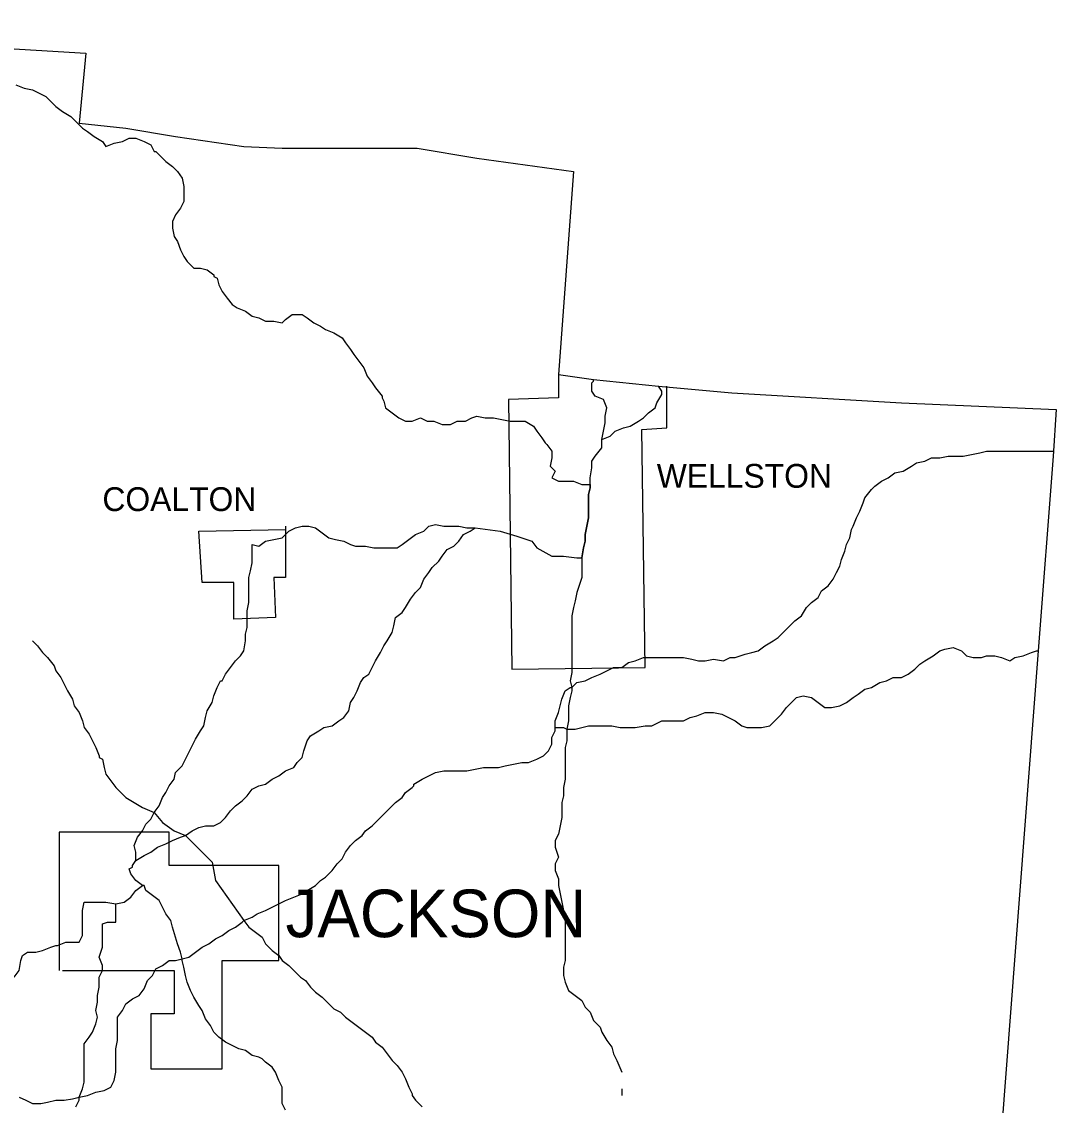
# Model space of a CAD drawing. Extents: x 0 to 40.2, y 0 to 22.
# Drawn here: x 7.207 to 8.054, y 17.657 to 18.545 of the extents above; entities that cross this region are included whole.
import ezdxf

# ---------------------------------------------------------------- set-up
doc = ezdxf.new("R2010")
doc.units = 0
doc.layers.add('Default', color=7, linetype='Continuous')

msp = doc.modelspace()

# ---------------------------------------------------------------- linework, layer by layer
at = {"layer": 'Default'}
for points in [[(6.86238, 18.54502), (7.0369, 18.53275), (7.11189, 18.52866), (7.14597, 18.52593), (7.25914, 18.51912), (7.25368, 18.46185), (7.29186, 18.45776), (7.33276, 18.45095), (7.38866, 18.44277), (7.42002, 18.4414), (7.47729, 18.4414), (7.53046, 18.4414), (7.57954, 18.43322), (7.65862, 18.42231), (7.64635, 18.25598)], [(7.20187, 18.49321), (7.20869, 18.49049), (7.21551, 18.48912), (7.22096, 18.4864), (7.22642, 18.48367), (7.23051, 18.47958), (7.2346, 18.47549), (7.24005, 18.4714), (7.24687, 18.46731), (7.25096, 18.46322), (7.25641, 18.45776), (7.2605, 18.45504), (7.26596, 18.45095), (7.27277, 18.44686), (7.2755, 18.44277), (7.28232, 18.44549), (7.28913, 18.44686), (7.29459, 18.44958), (7.30004, 18.44958), (7.30686, 18.44686), (7.31231, 18.44413), (7.31504, 18.43868)], [(7.31504, 18.43868), (7.3164, 18.43868), (7.3164, 18.43868), (7.32049, 18.43459), (7.32458, 18.43049), (7.33004, 18.4264), (7.33413, 18.42231), (7.33822, 18.41686), (7.33958, 18.41004), (7.33958, 18.40459), (7.33958, 18.39777), (7.33685, 18.39232), (7.33276, 18.38687), (7.33004, 18.38141), (7.33004, 18.37596), (7.3314, 18.36914), (7.33413, 18.36505), (7.33685, 18.35823), (7.33958, 18.35278), (7.34231, 18.34869), (7.34776, 18.34324), (7.35321, 18.34324), (7.35867, 18.34187), (7.36412, 18.33778)], [(7.36412, 18.33778), (7.36412, 18.33642), (7.36412, 18.33642), (7.36685, 18.33506), (7.36821, 18.3296), (7.37094, 18.32415), (7.37503, 18.31869), (7.37912, 18.31324), (7.38321, 18.31051), (7.39003, 18.30779), (7.39548, 18.3037), (7.40093, 18.30233), (7.40639, 18.29961), (7.4132, 18.29961), (7.42002, 18.29824), (7.42275, 18.30097), (7.4282, 18.30506), (7.43638, 18.30506), (7.44047, 18.30233), (7.44593, 18.29824), (7.45138, 18.29552), (7.45547, 18.29279), (7.46229, 18.29006), (7.4691, 18.28597), (7.47183, 18.28188), (7.47592, 18.27643), (7.47865, 18.27234), (7.48274, 18.26688), (7.48683, 18.26143), (7.48956, 18.25461), (7.49365, 18.24916), (7.49637, 18.24507), (7.50183, 18.23825)], [(7.64635, 18.25598), (7.64635, 18.23689), (7.60545, 18.23553), (7.60817, 18.01465), (7.71725, 18.01601), (7.71452, 18.21098), (7.73497, 18.21235), (7.73497, 18.24643)], [(7.64635, 18.25598), (7.67498, 18.25189), (7.72815, 18.24643), (7.78815, 18.24098), (7.92721, 18.2328), (8.05401, 18.22735)], [(7.6818, 18.2028), (7.68316, 18.20962), (7.68453, 18.21644), (7.68453, 18.22189), (7.68589, 18.22871), (7.68316, 18.23553), (7.67634, 18.23825), (7.67362, 18.24234), (7.67362, 18.24916), (7.67498, 18.25052), (7.67498, 18.25189)], [(7.6818, 18.2028), (7.68862, 18.20553), (7.69271, 18.20962), (7.69952, 18.21235), (7.70498, 18.21371), (7.71179, 18.2178), (7.71588, 18.22053), (7.71997, 18.22462), (7.72543, 18.22871), (7.72679, 18.2328), (7.73088, 18.23962), (7.73088, 18.24234), (7.72815, 18.24643)], [(7.50183, 18.23825), (7.50183, 18.23689), (7.50319, 18.23416), (7.50455, 18.22871), (7.51001, 18.22462), (7.51546, 18.22053), (7.52091, 18.2178), (7.52637, 18.2178), (7.53319, 18.22053), (7.53864, 18.2178), (7.54409, 18.2178), (7.55091, 18.21507), (7.55773, 18.21507), (7.56318, 18.2178), (7.57, 18.2178), (7.57545, 18.22053), (7.57954, 18.22189), (7.58636, 18.22053), (7.59318, 18.22053), (7.59999, 18.21916), (7.60681, 18.2178), (7.61363, 18.2178), (7.61908, 18.2178), (7.6259, 18.21371), (7.62863, 18.20962), (7.63272, 18.20417), (7.63544, 18.20008)], [(8.05401, 18.22735), (8.05129, 18.18917), (8.03901, 18.02965), (8.00902, 17.63698), (7.9872, 17.36294), (7.96948, 17.16524), (7.96812, 17.14206), (7.9463, 16.89937), (7.68044, 16.92528), (7.52501, 16.93891)], [(7.63544, 18.20008), (7.63681, 18.19871), (7.6409, 18.19326), (7.6409, 18.18781), (7.63953, 18.18099), (7.64362, 18.1769), (7.6409, 18.17144), (7.64635, 18.16872), (7.6518, 18.16872), (7.65862, 18.16872), (7.66544, 18.16599), (7.67225, 18.16599)], [(7.67225, 18.16599), (7.67225, 18.17144), (7.67362, 18.17963), (7.67362, 18.18508), (7.67634, 18.18917), (7.6818, 18.19599), (7.6818, 18.20144), (7.6818, 18.2028), (7.6818, 18.2028)], [(7.88768, 18.13191), (7.8904, 18.13872), (7.89313, 18.14418), (7.89586, 18.15099), (7.89722, 18.15508), (7.90267, 18.1619), (7.9054, 18.16463), (7.91085, 18.16872), (7.91631, 18.17144), (7.92176, 18.17554), (7.92858, 18.1769), (7.93539, 18.18099), (7.93949, 18.18372), (7.9463, 18.18508), (7.95176, 18.18781), (7.95857, 18.18781), (7.96539, 18.18917), (7.97084, 18.18917), (7.97766, 18.18917), (7.98448, 18.19053), (7.9913, 18.1919), (7.99675, 18.19326), (8.00357, 18.19326), (8.01038, 18.19326), (8.01584, 18.19326), (8.02265, 18.19326), (8.02947, 18.19326), (8.03629, 18.19326), (8.04311, 18.19326), (8.04992, 18.19326), (8.05129, 18.19326)], [(7.66544, 18.106), (7.6668, 18.11418), (7.66816, 18.11963), (7.66816, 18.12509), (7.66953, 18.13191), (7.67089, 18.13872), (7.67089, 18.14418), (7.67089, 18.15099), (7.67089, 18.15781), (7.67225, 18.16326), (7.67225, 18.16599)], [(7.67225, 18.16599), (7.67225, 18.16326), (7.67089, 18.15781), (7.67089, 18.15099), (7.67089, 18.14418), (7.67089, 18.13872), (7.66953, 18.13191), (7.66816, 18.12509), (7.66816, 18.11963), (7.6668, 18.11418), (7.66544, 18.106)], [(7.42275, 18.13191), (7.42275, 18.08964), (7.4132, 18.08964), (7.41457, 18.05692), (7.38048, 18.05555), (7.38048, 18.08555), (7.35458, 18.08555), (7.35185, 18.12782), (7.42275, 18.12918)], [(7.39548, 18.11691), (7.40093, 18.11554), (7.40639, 18.11963), (7.4132, 18.121), (7.42002, 18.12236), (7.42548, 18.12782), (7.43093, 18.13054), (7.43638, 18.13191), (7.44184, 18.13191), (7.44729, 18.13054), (7.45274, 18.12645), (7.4582, 18.12236), (7.46365, 18.121), (7.47047, 18.11963), (7.47592, 18.11691), (7.48001, 18.11554), (7.48138, 18.11554)], [(7.48138, 18.11554), (7.48819, 18.11554), (7.49501, 18.11418), (7.50183, 18.11418), (7.50864, 18.11418), (7.5141, 18.11418), (7.51819, 18.11691), (7.52364, 18.121), (7.5291, 18.12509), (7.53591, 18.12782), (7.54, 18.13191), (7.54546, 18.13327), (7.55227, 18.13191), (7.55909, 18.13191), (7.56454, 18.13191), (7.57136, 18.13054), (7.57818, 18.13054), (7.57818, 18.13054)], [(7.4841, 18.00374), (7.48683, 18.00783), (7.49092, 18.01056), (7.49365, 18.01601), (7.49637, 18.02147), (7.50046, 18.02829), (7.50319, 18.03374), (7.50592, 18.03783), (7.51001, 18.04465), (7.51137, 18.0501), (7.51273, 18.05692), (7.51819, 18.06101), (7.52091, 18.0651), (7.52501, 18.07192), (7.5291, 18.07737), (7.53319, 18.08146), (7.53591, 18.08828), (7.54, 18.09373), (7.54273, 18.09782), (7.54818, 18.10327), (7.55091, 18.10736), (7.555, 18.11282), (7.56045, 18.11554), (7.56454, 18.11963), (7.56863, 18.12509), (7.57409, 18.12782), (7.57818, 18.13054), (7.57818, 18.13054)], [(7.57818, 18.13054), (7.59863, 18.12782), (7.61226, 18.12373), (7.62453, 18.11963), (7.62863, 18.11418), (7.6409, 18.10736), (7.65044, 18.10736), (7.66135, 18.106), (7.66544, 18.106)], [(7.77315, 18.02283), (7.78133, 18.02147), (7.78678, 18.0242), (7.79087, 18.0242), (7.79905, 18.02692), (7.80451, 18.02829), (7.80996, 18.02965), (7.81541, 18.03374), (7.82223, 18.03783), (7.82632, 18.04056), (7.83177, 18.04601), (7.83723, 18.05146), (7.83996, 18.05419), (7.84541, 18.05828), (7.8495, 18.0651), (7.85359, 18.06919), (7.85904, 18.07328), (7.86177, 18.07873), (7.86722, 18.08282), (7.87131, 18.08828), (7.87404, 18.09373), (7.87677, 18.09918), (7.87813, 18.10464), (7.88086, 18.11145), (7.88222, 18.11691), (7.88495, 18.12236), (7.88631, 18.12918), (7.88768, 18.13191)], [(7.37094, 18.00511), (7.37367, 18.01056), (7.37776, 18.01601), (7.38185, 18.02147), (7.38594, 18.02556), (7.38866, 18.02965), (7.39003, 18.03783), (7.39003, 18.04328), (7.39139, 18.04874), (7.39139, 18.05555), (7.39139, 18.06237), (7.39275, 18.06919), (7.39275, 18.07601), (7.39275, 18.08146), (7.39275, 18.08964), (7.39412, 18.09509), (7.39548, 18.10191), (7.39548, 18.10736), (7.39548, 18.11418), (7.39548, 18.11554), (7.39548, 18.11691)], [(7.66544, 18.106), (7.66544, 18.10191), (7.66544, 18.09509), (7.66544, 18.08964), (7.66271, 18.08146), (7.66135, 18.07737), (7.65998, 18.07055), (7.65862, 18.0651), (7.65726, 18.05828), (7.65726, 18.05283), (7.65726, 18.04465), (7.65726, 18.03783), (7.65726, 18.03101), (7.65726, 18.02556), (7.65726, 18.01874), (7.65726, 18.01192), (7.65589, 18.00511), (7.65726, 17.99965)], [(7.21551, 18.03783), (7.2196, 18.03374), (7.22369, 18.02829), (7.22778, 18.0242), (7.23323, 18.01738), (7.2346, 18.01329), (7.23869, 18.00783), (7.24141, 18.00238), (7.24414, 17.99693), (7.24823, 17.99011), (7.24959, 17.98466), (7.25368, 17.9792), (7.25641, 17.97239), (7.25777, 17.96693), (7.26186, 17.96148), (7.26459, 17.95602), (7.26732, 17.95057), (7.27005, 17.94375), (7.27005, 17.94239), (7.27277, 17.94103), (7.27277, 17.94103)], [(7.89177, 17.9942), (7.89722, 17.99829), (7.90267, 17.99965), (7.90949, 18.00374), (7.91494, 18.00511), (7.9204, 18.00783), (7.92721, 18.00783), (7.93267, 18.01056), (7.93812, 18.01465), (7.94221, 18.01874), (7.9463, 18.02147), (7.95312, 18.02556), (7.95857, 18.02965), (7.96266, 18.03101), (7.96948, 18.03238), (7.9763, 18.02965), (7.98039, 18.02556), (7.98584, 18.0242), (7.99266, 18.0242), (7.99675, 18.02556), (8.00357, 18.02556), (8.00902, 18.0242), (8.01584, 18.02147), (8.01993, 18.0242), (8.02674, 18.02556), (8.03356, 18.02829), (8.03765, 18.02965), (8.03765, 18.02965), (8.03901, 18.02965)], [(7.65726, 17.99965), (7.66135, 18.00374), (7.66816, 18.00511), (7.67362, 18.00783), (7.68044, 18.01056), (7.68589, 18.01329), (7.69134, 18.01601), (7.69816, 18.01601), (7.70361, 18.02011), (7.70907, 18.02147), (7.71588, 18.0242), (7.72134, 18.0242), (7.72679, 18.0242), (7.73497, 18.0242), (7.74179, 18.0242), (7.74861, 18.0242), (7.75542, 18.02283), (7.76088, 18.02147), (7.76633, 18.02147), (7.77315, 18.02283), (7.77315, 18.02283)], [(7.29868, 17.87013), (7.3014, 17.87695), (7.30549, 17.8824), (7.30822, 17.88785), (7.31231, 17.89194), (7.31504, 17.8974), (7.31913, 17.90285), (7.32186, 17.90967), (7.32458, 17.91376), (7.32731, 17.91921), (7.3314, 17.92467), (7.33276, 17.93012), (7.33822, 17.93557), (7.34094, 17.94103), (7.34367, 17.94648), (7.3464, 17.95193), (7.34912, 17.95739), (7.35321, 17.9642), (7.35594, 17.9683), (7.3573, 17.97511), (7.35867, 17.98057), (7.36276, 17.98738), (7.36412, 17.99284), (7.36685, 17.99965), (7.36958, 18.00511), (7.37094, 18.00511), (7.37094, 18.00511)], [(7.30004, 17.85786), (7.30686, 17.86195), (7.31231, 17.86468), (7.31777, 17.86877), (7.32458, 17.87149), (7.33004, 17.87422), (7.33685, 17.87695), (7.34094, 17.87831), (7.3464, 17.8824), (7.35185, 17.88513), (7.3573, 17.88649), (7.36412, 17.88649), (7.36958, 17.88922), (7.37367, 17.89331), (7.37776, 17.89876), (7.38185, 17.90285), (7.3873, 17.90694), (7.39139, 17.91103), (7.39548, 17.91649), (7.40093, 17.91921), (7.40639, 17.92058), (7.41184, 17.92467), (7.41729, 17.92739), (7.42275, 17.93148), (7.42957, 17.93421), (7.43229, 17.9383), (7.43638, 17.94239), (7.43775, 17.94784), (7.44047, 17.95602), (7.4432, 17.96011), (7.45002, 17.9642), (7.45411, 17.96693), (7.46092, 17.9683), (7.46638, 17.97239), (7.47047, 17.97511), (7.47456, 17.98057), (7.47592, 17.98738), (7.47865, 17.99147), (7.48138, 17.99693), (7.4841, 18.00374), (7.4841, 18.00374), (7.4841, 18.00374)], [(7.64362, 17.96693), (7.64362, 17.97239), (7.64635, 17.9792), (7.64771, 17.98466), (7.64908, 17.99011), (7.6518, 17.99693), (7.65589, 17.99965), (7.65726, 17.99965)], [(7.65726, 17.99965), (7.65726, 17.99693), (7.65589, 17.99147), (7.65453, 17.98466), (7.65453, 17.9792), (7.65453, 17.97239), (7.65317, 17.96557)], [(7.77315, 17.9792), (7.77996, 17.97784), (7.78542, 17.97511), (7.79087, 17.97239), (7.79633, 17.9683), (7.80042, 17.96693), (7.80723, 17.96693), (7.81269, 17.96693), (7.8195, 17.9683), (7.82359, 17.97239), (7.82905, 17.97784), (7.83314, 17.98329), (7.83723, 17.98738), (7.84132, 17.99147), (7.84677, 17.99284), (7.85359, 17.99147), (7.85904, 17.98738), (7.8645, 17.98329), (7.86995, 17.98329), (7.87677, 17.98466), (7.88222, 17.98738), (7.88768, 17.99147), (7.89177, 17.9942), (7.89177, 17.9942), (7.89177, 17.9942)], [(7.65317, 17.96557), (7.65998, 17.96557), (7.66544, 17.96693), (7.67089, 17.9683), (7.67771, 17.9683), (7.68453, 17.9683), (7.68998, 17.9683), (7.6968, 17.96693), (7.70225, 17.96693), (7.70907, 17.96693), (7.71725, 17.9683), (7.7227, 17.9683), (7.73088, 17.97239), (7.73497, 17.97239), (7.74179, 17.97239), (7.74861, 17.97239), (7.75406, 17.97511), (7.75951, 17.97648), (7.76633, 17.9792), (7.77178, 17.9792), (7.77315, 17.9792), (7.77315, 17.9792)], [(7.52773, 17.92058), (7.53455, 17.92467), (7.54, 17.92739), (7.54546, 17.93012), (7.55227, 17.93148), (7.55909, 17.93148), (7.56454, 17.93148), (7.57136, 17.93148), (7.57818, 17.93285), (7.585, 17.93421), (7.59181, 17.93421), (7.59727, 17.93421), (7.60272, 17.93557), (7.60954, 17.93694), (7.61635, 17.9383), (7.62181, 17.9383), (7.62863, 17.94103), (7.63408, 17.94375), (7.63817, 17.94784), (7.6409, 17.9533), (7.6409, 17.95875), (7.64362, 17.9642), (7.64362, 17.96693)], [(7.52773, 17.92058), (7.53455, 17.92467), (7.54, 17.92739), (7.54546, 17.93012), (7.55227, 17.93148), (7.55909, 17.93148), (7.56454, 17.93148), (7.57136, 17.93148), (7.57818, 17.93285), (7.585, 17.93421), (7.59181, 17.93421), (7.59727, 17.93421), (7.60272, 17.93557), (7.60954, 17.93694), (7.61635, 17.9383), (7.62181, 17.9383), (7.62863, 17.94103), (7.63408, 17.94375), (7.63817, 17.94784), (7.6409, 17.9533), (7.6409, 17.95875), (7.64362, 17.9642), (7.64362, 17.96693)], [(7.64362, 17.96693), (7.65044, 17.96693), (7.65317, 17.96557)], [(7.65317, 17.96557), (7.65317, 17.9642), (7.65317, 17.95602), (7.6518, 17.95057), (7.6518, 17.94375), (7.6518, 17.9383), (7.6518, 17.93148), (7.6518, 17.92467), (7.65044, 17.91785), (7.65044, 17.91103), (7.64908, 17.90558), (7.64908, 17.89876), (7.64908, 17.89331), (7.64771, 17.88649), (7.64635, 17.87967), (7.64362, 17.87422), (7.64362, 17.86877), (7.64635, 17.86058), (7.64362, 17.85513), (7.64362, 17.84968), (7.64635, 17.84286), (7.64635, 17.83741), (7.64771, 17.83059), (7.64908, 17.82377), (7.65044, 17.81696)], [(7.27277, 17.94103), (7.27414, 17.93421), (7.2755, 17.92876), (7.27959, 17.9233), (7.28368, 17.91785), (7.29186, 17.90967), (7.30549, 17.90149), (7.31504, 17.8974), (7.32186, 17.88922), (7.3314, 17.8824), (7.34094, 17.87831), (7.36276, 17.85649), (7.36548, 17.8415), (7.38866, 17.80877)], [(7.38866, 17.80877), (7.39548, 17.8115), (7.39957, 17.81423), (7.40639, 17.81696), (7.41184, 17.81968), (7.41729, 17.82241), (7.42275, 17.82514), (7.42957, 17.82786), (7.43638, 17.83059), (7.44047, 17.83332), (7.44729, 17.83741), (7.45138, 17.8415), (7.45547, 17.84422), (7.46092, 17.84968), (7.46501, 17.85513), (7.4691, 17.85922), (7.47183, 17.86468), (7.47592, 17.87013), (7.48001, 17.87422), (7.48547, 17.87831), (7.48819, 17.8824), (7.49365, 17.88649), (7.4991, 17.89194), (7.50319, 17.89603), (7.50728, 17.90012), (7.51273, 17.90558), (7.51819, 17.90967), (7.52091, 17.91376), (7.52637, 17.91785), (7.52773, 17.91921), (7.52773, 17.92058)], [(7.38866, 17.80877), (7.39548, 17.8115), (7.39957, 17.81423), (7.40639, 17.81696), (7.41184, 17.81968), (7.41729, 17.82241), (7.42275, 17.82514), (7.42957, 17.82786), (7.43638, 17.83059), (7.44047, 17.83332), (7.44729, 17.83741), (7.45138, 17.8415), (7.45547, 17.84422), (7.46092, 17.84968), (7.46501, 17.85513), (7.4691, 17.85922), (7.47183, 17.86468), (7.47592, 17.87013), (7.48001, 17.87422), (7.48547, 17.87831), (7.48819, 17.8824), (7.49365, 17.88649), (7.4991, 17.89194), (7.50319, 17.89603), (7.50728, 17.90012), (7.51273, 17.90558), (7.51819, 17.90967), (7.52091, 17.91376), (7.52637, 17.91785), (7.52773, 17.91921), (7.52773, 17.92058)], [(7.24005, 17.76787), (7.3314, 17.76787), (7.3314, 17.73242), (7.31231, 17.73242), (7.31231, 17.68743), (7.37094, 17.68743), (7.37094, 17.77605), (7.41729, 17.77605), (7.41729, 17.85377), (7.32731, 17.85377), (7.32731, 17.88104), (7.23732, 17.88104), (7.23732, 17.76787)], [(7.30004, 17.85786), (7.30004, 17.86468), (7.29868, 17.87013)], [(7.30549, 17.83741), (7.30004, 17.8415), (7.29595, 17.84695), (7.29459, 17.85104), (7.29731, 17.8524)], [(7.29731, 17.8524), (7.29731, 17.85377), (7.30004, 17.85786)], [(7.28368, 17.82241), (7.2905, 17.82377), (7.29595, 17.82786), (7.30004, 17.83332), (7.30549, 17.83741), (7.30549, 17.83741)], [(7.33822, 17.77742), (7.33685, 17.78287), (7.33413, 17.78969), (7.33276, 17.79514), (7.33004, 17.80332), (7.32867, 17.80877), (7.32458, 17.81423), (7.32186, 17.81968), (7.31913, 17.82514), (7.31367, 17.82923), (7.30822, 17.83332), (7.30686, 17.83741), (7.30549, 17.83741)], [(7.23596, 17.78832), (7.24278, 17.79105), (7.24823, 17.79105), (7.25368, 17.79105), (7.25641, 17.7965), (7.25641, 17.80332), (7.25641, 17.81014), (7.25641, 17.81696), (7.25777, 17.82377), (7.26459, 17.82377), (7.27005, 17.82377), (7.2755, 17.82377), (7.28368, 17.82241)], [(7.25368, 17.66425), (7.25641, 17.67107), (7.25777, 17.67652), (7.25777, 17.68334), (7.25777, 17.69016), (7.25777, 17.69697), (7.25777, 17.70243), (7.25777, 17.70788), (7.26186, 17.71334), (7.26459, 17.71743), (7.26732, 17.72424), (7.26868, 17.7297), (7.26732, 17.73515), (7.26868, 17.74197), (7.26868, 17.74742), (7.27005, 17.75424), (7.27005, 17.76242), (7.27277, 17.76787), (7.27277, 17.77196), (7.27005, 17.77878), (7.27277, 17.78696), (7.27277, 17.79378), (7.27277, 17.79923), (7.27277, 17.80605), (7.27686, 17.80741), (7.28368, 17.80741), (7.28368, 17.81287), (7.28368, 17.81968), (7.28368, 17.82105), (7.28368, 17.82241)], [(7.65044, 17.81696), (7.65044, 17.81696), (7.6518, 17.81423), (7.6518, 17.80877), (7.6518, 17.80059), (7.6518, 17.79514), (7.6518, 17.78969), (7.6518, 17.78287), (7.6518, 17.77605), (7.65044, 17.7706), (7.65044, 17.76378), (7.6518, 17.75833), (7.65453, 17.75151), (7.65998, 17.74742), (7.66544, 17.74333), (7.66816, 17.73788), (7.67225, 17.73379), (7.67498, 17.72697), (7.68044, 17.72152), (7.6818, 17.71743), (7.68589, 17.71061), (7.68998, 17.70515), (7.69134, 17.6997), (7.69407, 17.69425), (7.69816, 17.6847)], [(7.33822, 17.77742), (7.34367, 17.77878), (7.34912, 17.78287), (7.35458, 17.78696), (7.36003, 17.78969), (7.36548, 17.79378), (7.37094, 17.7965), (7.37639, 17.80059), (7.38185, 17.80332), (7.3873, 17.80741), (7.38866, 17.80877)], [(7.33822, 17.77742), (7.34367, 17.77878), (7.34912, 17.78287), (7.35458, 17.78696), (7.36003, 17.78969), (7.36548, 17.79378), (7.37094, 17.7965), (7.37639, 17.80059), (7.38185, 17.80332), (7.3873, 17.80741), (7.38866, 17.80877)], [(7.38866, 17.80877), (7.39275, 17.80332), (7.39821, 17.79923), (7.40366, 17.79514), (7.40639, 17.78969), (7.41184, 17.78423), (7.41729, 17.78014), (7.42002, 17.77605), (7.42548, 17.77196), (7.42957, 17.76787), (7.43502, 17.76242), (7.43911, 17.75969), (7.4432, 17.75424), (7.44729, 17.75015), (7.45274, 17.74606), (7.4582, 17.7406), (7.46229, 17.73651), (7.46774, 17.73379), (7.47183, 17.7297), (7.47729, 17.72561), (7.48274, 17.72152), (7.48819, 17.71743), (7.49365, 17.71334), (7.49637, 17.70925), (7.50183, 17.70515), (7.50592, 17.6997), (7.51001, 17.69425), (7.5141, 17.69016), (7.51819, 17.6847), (7.52091, 17.67925), (7.52364, 17.67243), (7.52637, 17.66698), (7.52637, 17.66562)], [(7.20051, 17.76242), (7.2046, 17.76787), (7.20596, 17.77605), (7.20733, 17.78014), (7.21142, 17.78287), (7.21824, 17.78287), (7.22369, 17.78423), (7.23051, 17.78696), (7.2346, 17.78832), (7.23596, 17.78832)], [(7.25368, 17.66425), (7.2605, 17.66562), (7.26732, 17.66834), (7.27414, 17.66971), (7.27959, 17.67243), (7.28232, 17.67789), (7.28368, 17.6847), (7.28368, 17.69016), (7.28368, 17.69697), (7.28368, 17.70379), (7.28504, 17.71061), (7.28504, 17.71743), (7.28504, 17.72288), (7.28504, 17.7297), (7.28913, 17.73515), (7.29186, 17.7406), (7.29731, 17.74469), (7.30277, 17.74742), (7.30686, 17.75287), (7.30958, 17.75969), (7.31367, 17.76378), (7.3164, 17.76924), (7.32186, 17.77196), (7.32731, 17.77605), (7.33276, 17.77605), (7.33822, 17.77742), (7.33822, 17.77742)], [(7.25368, 17.66425), (7.2605, 17.66562), (7.26732, 17.66834), (7.27414, 17.66971), (7.27959, 17.67243), (7.28232, 17.67789), (7.28368, 17.6847), (7.28368, 17.69016), (7.28368, 17.69697), (7.28368, 17.70379), (7.28504, 17.71061), (7.28504, 17.71743), (7.28504, 17.72288), (7.28504, 17.7297), (7.28913, 17.73515), (7.29186, 17.7406), (7.29731, 17.74469), (7.30277, 17.74742), (7.30686, 17.75287), (7.30958, 17.75969), (7.31367, 17.76378), (7.3164, 17.76924), (7.32186, 17.77196), (7.32731, 17.77605), (7.33276, 17.77605), (7.33822, 17.77742), (7.33822, 17.77742)], [(7.40093, 17.69697), (7.39548, 17.69834), (7.39003, 17.70243), (7.38457, 17.70379), (7.37912, 17.70652), (7.37367, 17.70925), (7.36821, 17.71334), (7.36412, 17.71743), (7.36139, 17.72288), (7.3573, 17.72833), (7.35458, 17.73515), (7.35185, 17.73924), (7.34776, 17.74606), (7.34503, 17.75151), (7.34231, 17.75833), (7.34094, 17.76378), (7.33958, 17.7706), (7.33822, 17.77605), (7.33822, 17.77742)], [(7.42275, 17.65334), (7.42002, 17.6588), (7.42002, 17.66562), (7.42002, 17.67243), (7.41729, 17.67789), (7.41457, 17.6847), (7.41184, 17.68879), (7.40639, 17.69288), (7.40366, 17.69561), (7.40093, 17.69697)], [(7.2046, 17.66425), (7.21005, 17.66153), (7.21551, 17.6588), (7.22233, 17.6588), (7.22778, 17.66016), (7.2346, 17.66153), (7.24141, 17.66153), (7.24823, 17.66289), (7.25368, 17.66425), (7.25368, 17.66425)], [(7.2046, 17.66425), (7.21005, 17.66153), (7.21551, 17.6588), (7.22233, 17.6588), (7.22778, 17.66016), (7.2346, 17.66153), (7.24141, 17.66153), (7.24823, 17.66289), (7.25368, 17.66425), (7.25368, 17.66425)], [(7.25096, 17.65607), (7.25368, 17.66153), (7.25368, 17.66425)], [(7.52637, 17.66562), (7.5291, 17.66153), (7.53455, 17.65607)], [(7.69816, 17.67107), (7.69816, 17.66562)]]:
    msp.add_lwpolyline(points, dxfattribs=at)

# ---------------------------------------------------------------- texts
for s, height, p in [('WELLSTON', 0.019502, (7.72679, 18.16326)), ('COALTON', 0.019502, (7.27277, 18.14418)), ('JACKSON', 0.039005, (7.42275, 17.79514))]:
    msp.add_text(s, height=height, dxfattribs=at).set_placement(p)

doc.saveas('drawing.dxf')
